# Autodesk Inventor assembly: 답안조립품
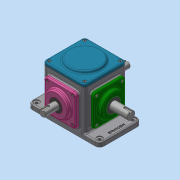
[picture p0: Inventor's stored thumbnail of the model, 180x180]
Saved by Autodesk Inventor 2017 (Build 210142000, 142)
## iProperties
Part Number: 답안조립품
Material: 일반
Document SubType Name: Assembly
Designer: MRC
Author: MRC
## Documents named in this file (16)
- C:\Users\MRC\Desktop\620307V1003\답안조립품.iam
- C:\Users\MRC\Desktop\620307V1003\본체.ipt
- C:\Users\MRC\Desktop\620307V1003\개스킷.ipt
- C:\Users\MRC\Desktop\620307V1003\메인베벨기어.ipt
- C:\Users\MRC\Desktop\620307V1003\메인축.ipt
- C:\Users\MRC\Desktop\620307V1003\메인커버.ipt
- C:\Users\MRC\Desktop\620307V1003\베어링 6203.ipt
- C:\Users\MRC\Desktop\620307V1003\베어링 6204.ipt
- C:\Users\MRC\Desktop\620307V1003\볼트 M4.ipt
- C:\Users\MRC\Desktop\620307V1003\상부커버.ipt
- C:\Users\MRC\Desktop\620307V1003\서브베벨기어.ipt
- C:\Users\MRC\Desktop\620307V1003\서브축.ipt
- C:\Users\MRC\Desktop\620307V1003\서브커버.ipt
- C:\Users\MRC\Desktop\620307V1003\오일 실 17 32 8.ipt
- C:\Users\MRC\Desktop\620307V1003\오일 실 20 35 8.ipt
- C:\Users\MRC\Desktop\620307V1003\키 4x4.ipt
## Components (1 placed, 1 different names)
1. 개스킷:1
